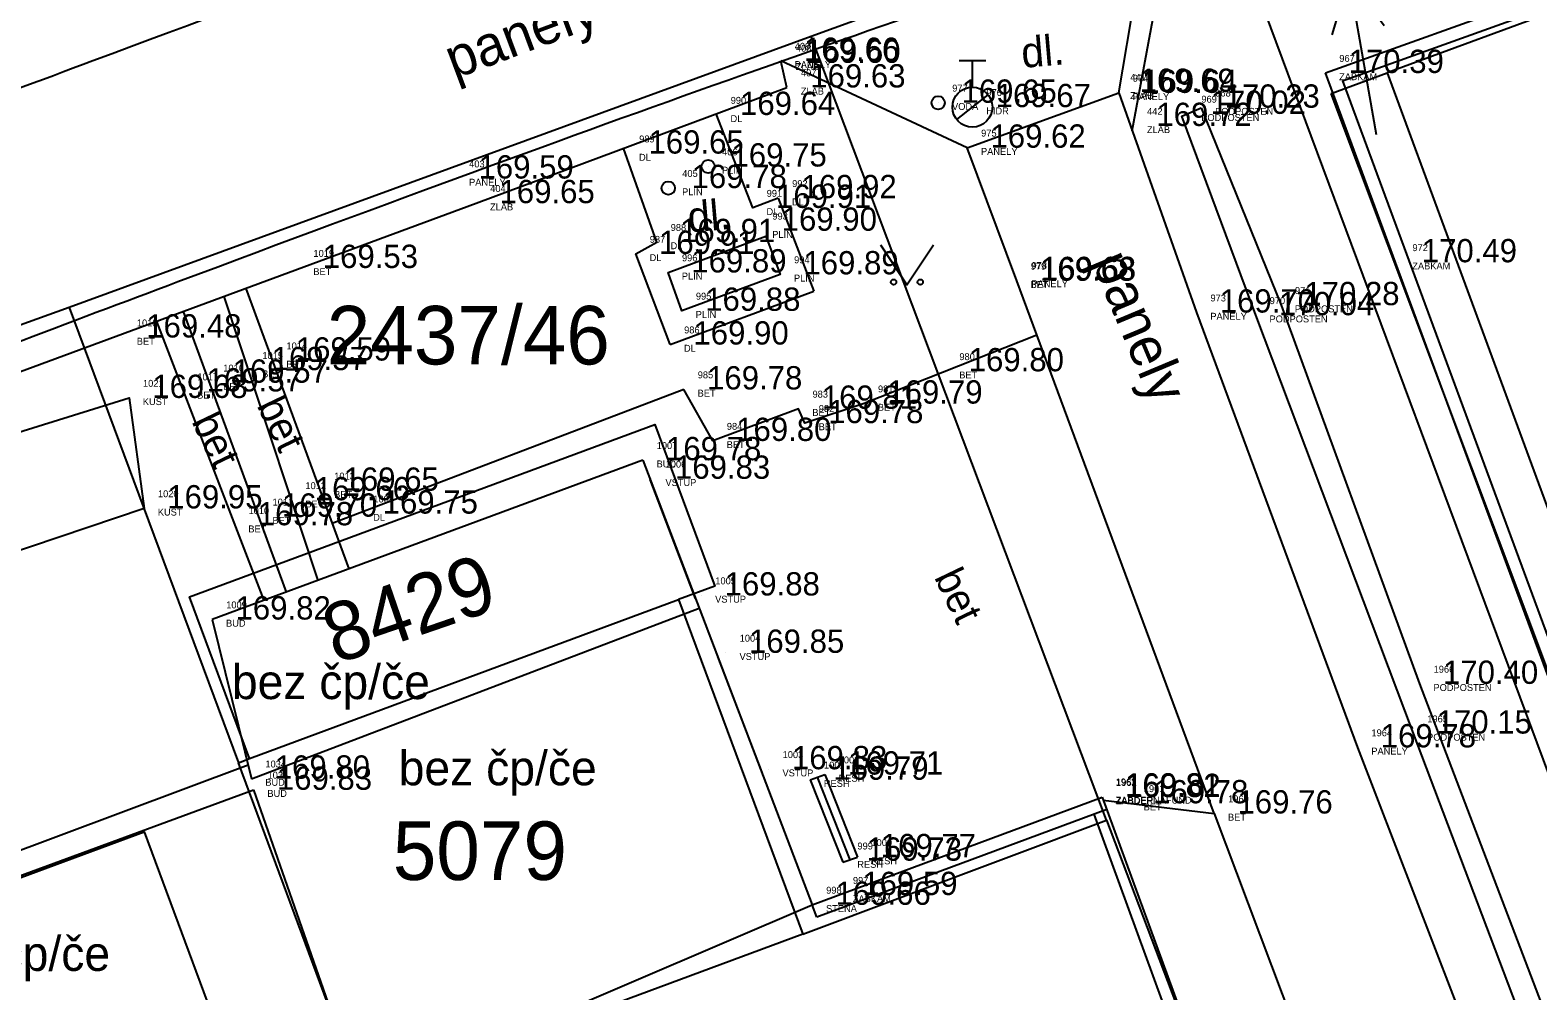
# Model space of a CAD drawing. Extents: x -566117 to -565580, y -1202428 to -1201938.
# Drawn here: x -565937.36 to -565909.04, y -1202072.35 to -1202054.29 of the extents above; entities that cross this region are included whole.
import ezdxf

# ---------------------------------------------------------------- set-up
doc = ezdxf.new("R2010")
doc.units = 0
for name, color, linetype in [('1029', 7, 'Continuous'), ('Bod', 7, 'Continuous'), ('BUDOVY_MĚŘ (Construction)', 7, 'Continuous'), ('BUOVY_NEMĚŘ', 7, 'Continuous'), ('CIZÍ_NADZEM', 7, 'Continuous'), ('Implicitní', 7, 'Continuous'), ('Katastr', 7, 'Continuous'), ('Kod', 7, 'Continuous'), ('Oplocení', 7, 'Continuous'), ('Plin', 7, 'Continuous'), ('POMOC_POPIS', 7, 'Continuous'), ('Voda', 7, 'Continuous'), ('Výška', 7, 'Continuous'), ('ZELEŇ', 7, 'Continuous'), ('ZN_KULTUR', 7, 'Continuous'), ('Zpevněné plohy', 7, 'Continuous'), ('Číslo', 7, 'Continuous'), ('Číslo popisné', 7, 'Continuous')]:
    doc.layers.add(name, color=color, linetype=linetype)

# ---------------------------------------------------------------- blocks, each defined once
blk = doc.blocks.new('1029$2')
at = {"layer": 'Katastr'}
for p, q in [((0, 3.001), (-0.501, 2)), ((0, 0), (0, 3.001)), ((0, 3.001), (0.501, 2))]:
    blk.add_line(p, q, dxfattribs=at)
blk = doc.blocks.new('A$C69D74C1E')
at = {"layer": 'Katastr'}
for p, q in [((149.9, 16.82), (142.24, 14.03)), ((181.01, -66.83), (149.9, 16.82)), ((161.72, 16.53), (153.06, 13.35)), ((142.24, 14.03), (128.3, 8.94)), ((147.79, -0.7), (142.24, 14.03)), ((152.01, 12.96), (153.06, 13.35)), ((153.06, 13.35), (163.41, -14.79)), ((128.3, 8.94), (114.22, 3.81)), ((128.3, 8.94), (131.48, 0.38)), ((131.69, 0.46), (139.75, 3.45)), ((139.75, 3.45), (142.08, -2.84)), ((131.48, 0.38), (131.69, 0.46)), ((133.3, -4.52), (131.48, 0.38)), ((142.08, -2.84), (147.79, -0.7)), ((147.79, -0.7), (150.48, -7.82)), ((142.08, -2.84), (133.81, -5.91))]:
    blk.add_line(p, q, dxfattribs=at)
for points in [[(165.44, -20.31), (164.61, -20.62), (152.01, 12.96)], [(131.69, 0.46), (130.56, 3.5), (139.3, 6.74), (140.43, 3.7), (139.75, 3.45)], [(125.11, -7.56), (123.5, -3.22), (129.71, -0.92), (131.32, -5.26)]]:
    blk.add_lwpolyline(points, dxfattribs=at)
at = {"layer": '1029', "rotation": 10}
blk.add_blockref('1029$2', (152.86, 12.18), dxfattribs=at)
at = {"layer": 'Katastr'}
for s, p in [('2437/46', (133.14, 7.867)), ('5079', (134.38, -1.823))]:
    blk.add_text(s, height=1.1, dxfattribs=at).set_placement(p)
blk.add_text('8429', height=1.1, rotation=19, dxfattribs=at).set_placement((133.311, 2.227))
blk = doc.blocks.new('6.130')
at = {"layer": 'Voda'}
for p, q in [((-0.5, 1.75), (0.5, 1.75)), ((0, 0.75), (0, 1.75)), ((-0.588, -0.462), (0.592, 0.464))]:
    blk.add_line(p, q, dxfattribs=at)
blk.add_circle((0, 0), 0.75, dxfattribs=at)
blk = doc.blocks.new('POINT_DISPLAY')
at = {"layer": 'Implicitní'}
blk.add_line((0, 0), (0, 0), dxfattribs=at)
blk = doc.blocks.new('3.140_2')
at = {"layer": 'ZN_KULTUR'}
blk.add_lwpolyline([(-1, 1.5), (0, 0), (1, 1.5)], dxfattribs=at)
for centre in [(-0.5, 0.1), (0.5, 0.1)]:
    blk.add_circle(centre, 0.1, dxfattribs=at)

msp = doc.modelspace()

# ---------------------------------------------------------------- linework, layer by layer
at = {"layer": 'BUDOVY_MĚŘ (Construction)'}
for p, q in [((-565925.855, -1202062.373), (-565933.942, -1202065.368)), ((-565925.855, -1202062.373), (-565922.67, -1202070.73)), ((-565933.942, -1202065.368), (-565933.205, -1202068.359)), ((-565941.47, -1202071.628), (-565933.165, -1202068.568))]:
    msp.add_line(p, q, dxfattribs=at)
at = {"layer": 'BUOVY_NEMĚŘ'}
for points in [[(-565933.205, -1202068.359), (-565924.795, -1202065.154)], [(-565933.165, -1202068.568), (-565931.63, -1202072.96), (-565939.889, -1202076.02)], [(-565931.63, -1202072.96), (-565931.115, -1202074.348), (-565922.67, -1202070.73)]]:
    msp.add_lwpolyline(points, dxfattribs=at)
at = {"layer": 'Implicitní'}
for p, q in [((-565922.711, -1202068.379), (-565922.435, -1202068.282)), ((-565922.711, -1202068.379), (-565922.096, -1202069.931)), ((-565922.435, -1202068.282), (-565921.821, -1202069.835)), ((-565922.096, -1202069.931), (-565921.821, -1202069.835))]:
    msp.add_line(p, q, dxfattribs=at)
msp.add_lwpolyline([(-565923.54, -1202058.161), (-565923.273, -1202058.88), (-565925.118, -1202059.565), (-565925.379, -1202058.844)], close=True, dxfattribs=at)
at = {"layer": 'Oplocení'}
for p, q in [((-565913.031, -1202055.095), (-565908.814, -1202053.58)), ((-565912.71, -1202055.243), (-565908.729, -1202053.816)), ((-565903.439, -1202081.099), (-565913.031, -1202055.095)), ((-565912.71, -1202055.243), (-565903.291, -1202080.778)), ((-565924.864, -1202064.974), (-565925.717, -1202062.734)), ((-565924.449, -1202066.063), (-565923.618, -1202068.243)), ((-565921.959, -1202069.883), (-565922.573, -1202068.33)), ((-565922.67, -1202070.73), (-565917.225, -1202068.705)), ((-565917.225, -1202068.705), (-565915.064, -1202074.62)), ((-565917.138, -1202068.94), (-565922.583, -1202070.965)), ((-565915.299, -1202074.705), (-565917.372, -1202069.027)), ((-565922.583, -1202070.965), (-565922.67, -1202070.73))]:
    msp.add_line(p, q, dxfattribs=at)
for points in [[(-565905.607, -1202082.801), (-565908.31, -1202075.616), (-565911.378, -1202067.511), (-565914.339, -1202059.648), (-565915.727, -1202055.909), (-565915.361, -1202055.747)], [(-565915.361, -1202055.747), (-565913.864, -1202059.459), (-565911.26, -1202066.577), (-565907.922, -1202075.341), (-565905.493, -1202081.913), (-565903.439, -1202081.099)]]:
    msp.add_lwpolyline(points, dxfattribs=at)
at = {"layer": 'Plin'}
for centre in [(-565924.625, -1202056.853), (-565925.374, -1202057.258)]:
    msp.add_circle(centre, 0.125, dxfattribs=at)
at = {"layer": 'Voda'}
msp.add_circle((-565920.304, -1202055.654), 0.125, dxfattribs=at)
at = {"layer": 'ZELEŇ'}
msp.add_lwpolyline([(-565948.838, -1202065.698), (-565943.491, -1202063.689), (-565935.504, -1202061.203), (-565935.223, -1202063.279), (-565944.247, -1202066.324), (-565948.65, -1202067.52), (-565945.971, -1202073.934), (-565947.372, -1202074.381), (-565949.96, -1202066.549), (-565948.838, -1202065.698)], dxfattribs=at)
at = {"layer": 'Zpevněné plohy'}
for p, q in [((-565916.911, -1202055.469), (-565916.401, -1202052.454)), ((-565916.659, -1202056.18), (-565916.024, -1202052.762)), ((-565919.76, -1202056.499), (-565923.262, -1202054.867)), ((-565923.145, -1202055.367), (-565923.262, -1202054.867)), ((-565928.983, -1202057.542), (-565923.145, -1202055.367)), ((-565919.76, -1202056.499), (-565916.911, -1202055.469)), ((-565918.828, -1202059.001), (-565919.76, -1202056.499)), ((-565945.528, -1202063.66), (-565928.983, -1202057.542)), ((-565923.31, -1202057.448), (-565922.641, -1202059.198)), ((-565915.119, -1202069.014), (-565918.828, -1202059.001)), ((-565933.721, -1202059.294), (-565931.955, -1202064.632)), ((-565933.312, -1202059.143), (-565931.374, -1202064.417)), ((-565925.34, -1202060.199), (-565922.641, -1202059.198)), ((-565934.488, -1202059.578), (-565932.55, -1202064.853)), ((-565934.989, -1202059.763), (-565932.975, -1202065.01)), ((-565925.084, -1202061.043), (-565931.687, -1202063.564)), ((-565942.055, -1202071.387), (-565933.268, -1202068.101)), ((-565917.204, -1202068.761), (-565915.119, -1202069.014)), ((-565915.119, -1202069.014), (-565912.321, -1202076.456))]:
    msp.add_line(p, q, dxfattribs=at)
for points in [[(-565916.911, -1202055.469), (-565915.451, -1202059.598), (-565912.427, -1202067.771), (-565909.215, -1202076.116), (-565906.527, -1202083.223), (-565903.134, -1202092.404)], [(-565923.31, -1202057.448), (-565923.788, -1202057.631), (-565924.473, -1202055.862)], [(-565925.34, -1202060.199), (-565925.984, -1202058.496), (-565925.591, -1202058.273), (-565926.216, -1202056.511)], [(-565918.451, -1202060.02), (-565921.697, -1202061.309), (-565922.809, -1202061.676), (-565922.928, -1202061.406), (-565924.537, -1202062.011), (-565925.084, -1202061.043)]]:
    msp.add_lwpolyline(points, dxfattribs=at)
for points in [[(-566046.233, -1202095.491), (-566045.931, -1202095.393), (-566043.978, -1202094.752), (-566040.389, -1202093.195), (-566035.531, -1202091.756), (-566028.975, -1202089.449), (-566022.404, -1202086.74), (-566013.877, -1202083.764), (-566006.988, -1202080.967), (-565999.231, -1202078.336), (-565993.39, -1202076.098), (-565982.391, -1202071.759), (-565967.94, -1202066.641), (-565949.498, -1202059.811), (-565935.388, -1202054.572), (-565926.049, -1202051.077), (-565917.958, -1202048.181), (-565909.827, -1202045.163), (-565898.95, -1202041.321), (-565888.732, -1202037.388), (-565879.759, -1202034.036), (-565869.081, -1202030.224), (-565859.242, -1202026.317), (-565849.297, -1202023.069), (-565843.932, -1202020.848), (-565836.631, -1202018.501), (-565830.04, -1202016.01), (-565822.89, -1202013.251), (-565816.476, -1202011.009), (-565808.989, -1202007.913), (-565802.143, -1202004.887), (-565798.059, -1202002.759), (-565793.947, -1202000.116), (-565789.34, -1201997.072), (-565785.134, -1201994.185), (-565781.539, -1201991.969), (-565778.045, -1201989.73), (-565773.319, -1201986.775), (-565768.281, -1201983.714), (-565761.544, -1201979.725), (-565754.374, -1201977.005), (-565748.201, -1201974.518), (-565743.713, -1201972.786), (-565741.115, -1201971.759), (-565739.444, -1201971.098)], [(-565976.764, -1202074.599), (-565975.068, -1202073.996), (-565970.908, -1202072.515), (-565960.65, -1202068.538), (-565946.466, -1202063.528), (-565932.832, -1202058.326), (-565923.028, -1202054.759), (-565915.71, -1202052.273), (-565903.782, -1202047.572), (-565889.735, -1202042.655), (-565875.782, -1202037.425), (-565865.226, -1202033.562), (-565857.124, -1202030.559), (-565849.222, -1202027.615), (-565843.807, -1202025.74), (-565838.67, -1202023.909), (-565834.175, -1202022.242), (-565830.509, -1202020.913), (-565828.358, -1202020.134)]]:
    msp.add_open_spline(points, degree=3, dxfattribs=at)

# ---------------------------------------------------------------- block references
at = {"layer": 'Bod'}
for p in [(-565923.262, -1202054.867), (-565923.237, -1202054.904), (-565913.031, -1202055.095), (-565923.145, -1202055.367), (-565920.304, -1202055.654), (-565916.958, -1202055.45), (-565916.911, -1202055.469), (-565924.465, -1202055.884), (-565919.662, -1202055.737), (-565915.623, -1202055.863), (-565915.361, -1202055.747), (-565916.643, -1202056.091), (-565919.76, -1202056.499), (-565926.183, -1202056.61), (-565924.625, -1202056.853), (-565929.377, -1202057.079), (-565925.374, -1202057.258), (-565928.983, -1202057.542), (-565923.788, -1202057.631), (-565923.31, -1202057.448), (-565925.591, -1202058.273), (-565923.681, -1202058.06), (-565925.984, -1202058.496), (-565932.303, -1202058.76), (-565925.379, -1202058.844), (-565911.657, -1202058.653), (-565923.273, -1202058.88), (-565918.828, -1202059.001), (-565918.813, -1202058.987), (-565925.118, -1202059.565), (-565915.451, -1202059.598), (-565914.339, -1202059.648), (-565913.864, -1202059.459), (-565935.619, -1202060.067), (-565925.34, -1202060.199), (-565932.81, -1202060.5), (-565933.262, -1202060.68), (-565920.168, -1202060.702), (-565934.483, -1202061.081), (-565933.996, -1202060.916), (-565925.084, -1202061.043), (-565935.504, -1202061.203), (-565921.697, -1202061.309), (-565922.928, -1202061.406), (-565922.809, -1202061.676), (-565924.537, -1202062.011), (-565925.855, -1202062.373), (-565925.686, -1202062.722), (-565931.912, -1202062.947), (-565935.223, -1202063.279), (-565932.453, -1202063.126), (-565931.178, -1202063.377), (-565933.522, -1202063.596), (-565933.071, -1202063.434), (-565924.754, -1202064.916), (-565933.942, -1202065.368), (-565924.296, -1202065.994), (-565911.26, -1202066.577), (-565911.378, -1202067.511), (-565912.427, -1202067.771), (-565923.488, -1202068.182), (-565933.205, -1202068.359), (-565922.711, -1202068.379), (-565922.435, -1202068.282), (-565933.165, -1202068.568), (-565917.232, -1202068.694), (-565917.225, -1202068.705), (-565916.704, -1202068.822), (-565915.119, -1202069.014), (-565921.821, -1202069.835), (-565922.083, -1202069.9), (-565922.67, -1202070.73), (-565922.168, -1202070.546)]:
    msp.add_blockref('POINT_DISPLAY', p, dxfattribs=at)
at = {"layer": 'CIZÍ_NADZEM', "xscale": 0.5, "yscale": 0.5}
msp.add_blockref('6.130', (-565919.662, -1202055.737), dxfattribs=at)
at = {"layer": 'Implicitní'}
msp.add_blockref('A$C69D74C1E', (-566064.93, -1202068.44), dxfattribs=at)
at = {"layer": 'ZN_KULTUR', "xscale": 0.5, "yscale": 0.5}
msp.add_blockref('3.140_2', (-565920.891, -1202059.074), dxfattribs=at)

# ---------------------------------------------------------------- texts
at = {"layer": 'Kod'}
for s, p in [('PANELY', (-565923.002, -1202055.002)), ('ZLAB', (-565922.978, -1202055.039)), ('ZABKAM', (-565912.772, -1202055.23)), ('ZLAB', (-565922.885, -1202055.501)), ('VODA', (-565920.044, -1202055.789)), ('ZLAB', (-565916.698, -1202055.585)), ('PANELY', (-565916.651, -1202055.603)), ('DL', (-565924.205, -1202056.018)), ('HIDR', (-565919.402, -1202055.872)), ('PODPOSTEN', (-565915.363, -1202055.997)), ('PODPOSTEN', (-565915.102, -1202055.881)), ('ZLAB', (-565916.383, -1202056.225)), ('PANELY', (-565919.5, -1202056.634)), ('DL', (-565925.924, -1202056.744)), ('PLIN', (-565924.365, -1202056.987)), ('PANELY', (-565929.117, -1202057.213)), ('PLIN', (-565925.115, -1202057.393)), ('ZLAB', (-565928.723, -1202057.677)), ('DL', (-565923.529, -1202057.766)), ('DL', (-565923.051, -1202057.583)), ('DL', (-565925.332, -1202058.407)), ('PLIN', (-565923.422, -1202058.195)), ('DL', (-565925.725, -1202058.631)), ('BET', (-565932.043, -1202058.895)), ('PLIN', (-565925.12, -1202058.978)), ('ZABKAM', (-565911.398, -1202058.787)), ('PLIN', (-565923.014, -1202059.015)), ('BET', (-565918.569, -1202059.136)), ('PANELY', (-565918.554, -1202059.121)), ('PLIN', (-565924.859, -1202059.699)), ('PANELY', (-565915.192, -1202059.733)), ('PODPOSTEN', (-565914.08, -1202059.783)), ('PODPOSTEN', (-565913.605, -1202059.593)), ('BET', (-565935.359, -1202060.202)), ('DL', (-565925.08, -1202060.334)), ('BET', (-565932.55, -1202060.634)), ('BET', (-565933.003, -1202060.815)), ('BET', (-565919.909, -1202060.836)), ('BET', (-565934.224, -1202061.215)), ('BET', (-565933.737, -1202061.05)), ('BET', (-565924.824, -1202061.178)), ('KUST', (-565935.245, -1202061.337)), ('BET', (-565921.438, -1202061.443)), ('BET', (-565922.668, -1202061.541)), ('BET', (-565922.549, -1202061.81)), ('BET', (-565924.277, -1202062.146)), ('BUD', (-565925.595, -1202062.508)), ('VSTUP', (-565925.427, -1202062.857)), ('BET', (-565931.652, -1202063.082)), ('KUST', (-565934.964, -1202063.413)), ('BET', (-565932.193, -1202063.261)), ('BET', (-565933.263, -1202063.73)), ('BET', (-565932.811, -1202063.569)), ('DL', (-565930.918, -1202063.512)), ('VSTUP', (-565924.494, -1202065.05)), ('BUD', (-565933.682, -1202065.502)), ('VSTUP', (-565924.036, -1202066.128)), ('PODPOSTEN', (-565911, -1202066.711)), ('PODPOSTEN', (-565911.119, -1202067.645)), ('PANELY', (-565912.168, -1202067.906)), ('VSTUP', (-565923.229, -1202068.316)), ('BUD', (-565932.945, -1202068.493)), ('RESH', (-565922.452, -1202068.513)), ('RESH', (-565922.176, -1202068.416)), ('BUD', (-565932.906, -1202068.702)), ('ZABDERNAFUND', (-565916.973, -1202068.828)), ('ZABDER', (-565916.965, -1202068.84)), ('BET', (-565916.445, -1202068.956)), ('BET', (-565914.86, -1202069.148)), ('RESH', (-565921.561, -1202069.969)), ('RESH', (-565921.824, -1202070.034)), ('STENA', (-565922.411, -1202070.865)), ('ZABKAM', (-565921.908, -1202070.68))]:
    msp.add_text(s, height=0.13, dxfattribs=at).set_placement(p)
at = {"layer": 'POMOC_POPIS'}
for s, height, rotation, p in [('panely', 0.75, 20.4762, (-565929.395, -1202055.215)), ('dl.', 0.57, 4.9059, (-565918.72, -1202055)), ('dl.', 0.57, 4.9059, (-565924.988, -1202058.094)), ('panely', 0.75, 292.7197, (-565917.428, -1202058.637)), ('bet', 0.55, 295.6453, (-565933.112, -1202061.342)), ('bet', 0.55, 295.6453, (-565934.337, -1202061.643)), ('bet', 0.55, 295.6453, (-565920.387, -1202064.57))]:
    msp.add_text(s, height=height, rotation=rotation, dxfattribs=at).set_placement(p)
at = {"layer": 'Výška'}
for s, p in [('169.66', (-565922.824, -1202054.867)), ('169.60', (-565922.8, -1202054.904)), ('170.39', (-565912.594, -1202055.095)), ('169.63', (-565922.707, -1202055.367)), ('169.69', (-565916.52, -1202055.45)), ('169.64', (-565916.473, -1202055.469)), ('169.64', (-565924.027, -1202055.884)), ('169.65', (-565919.866, -1202055.654)), ('169.67', (-565919.224, -1202055.737)), ('170.02', (-565915.185, -1202055.863)), ('170.23', (-565914.924, -1202055.747)), ('169.72', (-565916.205, -1202056.091)), ('169.65', (-565925.746, -1202056.61)), ('169.62', (-565919.322, -1202056.499)), ('169.75', (-565924.187, -1202056.853)), ('169.59', (-565928.939, -1202057.079)), ('169.78', (-565924.937, -1202057.258)), ('169.65', (-565928.545, -1202057.542)), ('169.92', (-565922.873, -1202057.448)), ('169.91', (-565923.351, -1202057.631)), ('169.90', (-565923.244, -1202058.06)), ('169.91', (-565925.154, -1202058.273)), ('169.91', (-565925.547, -1202058.496)), ('170.49', (-565911.22, -1202058.653)), ('169.53', (-565931.865, -1202058.76)), ('169.89', (-565924.942, -1202058.844)), ('169.89', (-565922.836, -1202058.88)), ('169.68', (-565918.391, -1202059.001)), ('169.68', (-565918.376, -1202058.987)), ('169.88', (-565924.681, -1202059.565)), ('170.28', (-565913.427, -1202059.459)), ('169.70', (-565915.014, -1202059.598)), ('170.04', (-565913.902, -1202059.648)), ('169.48', (-565935.181, -1202060.067)), ('169.90', (-565924.902, -1202060.199)), ('169.57', (-565932.825, -1202060.68)), ('169.59', (-565932.372, -1202060.5)), ('169.80', (-565919.731, -1202060.702)), ('169.57', (-565933.559, -1202060.916)), ('169.68', (-565935.067, -1202061.203)), ('169.57', (-565934.046, -1202061.081)), ('169.78', (-565924.646, -1202061.043)), ('169.81', (-565922.49, -1202061.406)), ('169.79', (-565921.26, -1202061.309)), ('169.78', (-565922.371, -1202061.676)), ('169.80', (-565924.099, -1202062.011)), ('169.78', (-565925.417, -1202062.373)), ('169.65', (-565931.474, -1202062.947)), ('169.83', (-565925.249, -1202062.722)), ('169.66', (-565932.015, -1202063.126)), ('169.95', (-565934.786, -1202063.279)), ('169.70', (-565932.633, -1202063.434)), ('169.75', (-565930.74, -1202063.377)), ('169.78', (-565933.085, -1202063.596)), ('169.88', (-565924.316, -1202064.916)), ('169.82', (-565933.504, -1202065.368)), ('169.85', (-565923.858, -1202065.994)), ('170.40', (-565910.822, -1202066.577)), ('169.78', (-565911.99, -1202067.771)), ('170.15', (-565910.941, -1202067.511)), ('169.83', (-565923.051, -1202068.182)), ('169.71', (-565921.998, -1202068.282)), ('169.80', (-565932.767, -1202068.359)), ('169.83', (-565932.728, -1202068.568)), ('169.79', (-565922.274, -1202068.379)), ('169.81', (-565916.795, -1202068.694)), ('169.82', (-565916.787, -1202068.705)), ('169.78', (-565916.267, -1202068.822)), ('169.76', (-565914.682, -1202069.014)), ('169.73', (-565921.646, -1202069.9)), ('169.77', (-565921.383, -1202069.835)), ('169.59', (-565921.73, -1202070.546)), ('169.66', (-565922.233, -1202070.73))]:
    msp.add_text(s, height=0.4375, dxfattribs=at).set_placement(p)
at = {"layer": 'Číslo'}
for s, p in [('409', (-565922.999, -1202054.658)), ('408', (-565922.975, -1202054.695)), ('967', (-565912.769, -1202054.886)), ('407', (-565922.882, -1202055.157)), ('441', (-565916.695, -1202055.241)), ('974', (-565916.648, -1202055.259)), ('977', (-565920.041, -1202055.445)), ('976', (-565919.399, -1202055.528)), ('968', (-565915.099, -1202055.537)), ('990', (-565924.202, -1202055.674)), ('969', (-565915.36, -1202055.653)), ('442', (-565916.38, -1202055.881)), ('989', (-565925.921, -1202056.4)), ('975', (-565919.497, -1202056.29)), ('406', (-565924.363, -1202056.643)), ('403', (-565929.115, -1202056.869)), ('405', (-565925.112, -1202057.049)), ('992', (-565923.048, -1202057.239)), ('404', (-565928.72, -1202057.333)), ('991', (-565923.526, -1202057.422)), ('988', (-565925.329, -1202058.064)), ('993', (-565923.419, -1202057.851)), ('987', (-565925.722, -1202058.287)), ('1019', (-565932.04, -1202058.551)), ('996', (-565925.117, -1202058.634)), ('994', (-565923.011, -1202058.671)), ('972', (-565911.395, -1202058.443)), ('979', (-565918.566, -1202058.792)), ('978', (-565918.551, -1202058.777)), ('971', (-565913.602, -1202059.249)), ('995', (-565924.856, -1202059.355)), ('973', (-565915.189, -1202059.389)), ('970', (-565914.077, -1202059.439)), ('1018', (-565935.357, -1202059.858)), ('986', (-565925.077, -1202059.99)), ('1014', (-565932.547, -1202060.29)), ('1015', (-565933, -1202060.471)), ('980', (-565919.906, -1202060.492)), ('1017', (-565934.221, -1202060.871)), ('1016', (-565933.734, -1202060.706)), ('985', (-565924.821, -1202060.834)), ('1021', (-565935.242, -1202060.993)), ('983', (-565922.665, -1202061.197)), ('981', (-565921.435, -1202061.099)), ('982', (-565922.547, -1202061.466)), ('984', (-565924.274, -1202061.802)), ('1007', (-565925.592, -1202062.164)), ('1006', (-565925.424, -1202062.513)), ('1012', (-565932.191, -1202062.917)), ('1013', (-565931.65, -1202062.738)), ('1020', (-565934.961, -1202063.069)), ('1011', (-565932.808, -1202063.225)), ('1008', (-565930.915, -1202063.168)), ('1010', (-565933.26, -1202063.386)), ('1005', (-565924.491, -1202064.706)), ('1009', (-565933.679, -1202065.158)), ('1004', (-565924.033, -1202065.784)), ('1966', (-565910.997, -1202066.367)), ('1965', (-565911.116, -1202067.301)), ('1964', (-565912.165, -1202067.562)), ('1003', (-565923.226, -1202067.972)), ('1034', (-565932.943, -1202068.149)), ('1001', (-565922.449, -1202068.169)), ('1002', (-565922.173, -1202068.072)), ('1035', (-565932.903, -1202068.358)), ('1963', (-565916.97, -1202068.485)), ('1962', (-565916.962, -1202068.496)), ('1961', (-565916.442, -1202068.612)), ('1960', (-565914.857, -1202068.804)), ('999', (-565921.821, -1202069.69)), ('1000', (-565921.558, -1202069.625)), ('998', (-565922.408, -1202070.521)), ('997', (-565921.906, -1202070.336))]:
    msp.add_text(s, height=0.13, dxfattribs=at).set_placement(p)
at = {"layer": 'Číslo popisné'}
for p in [(-565933.573, -1202066.863), (-565930.439, -1202068.483), (-565939.58, -1202071.972)]:
    msp.add_text('bez čp/če', height=0.65, dxfattribs=at).set_placement(p)

doc.saveas('drawing.dxf')
